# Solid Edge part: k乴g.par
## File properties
Author: priit
Template: Normal.par
Last saved by: Anon
Revision: 5
Application: Solid Edge
Accuracy: 0,990
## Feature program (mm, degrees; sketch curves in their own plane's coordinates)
sketch for "unnamed Protrusion 1" plane through (0, 0, 0) normal (0, -1, 0) x-axis (1, 0, 0)
  circle centre (0, 0) radius 2.25
extrude "unnamed Protrusion 1" add finite 7.5 symmetric
sketch for "ExtrudedCutout_1" plane through (0, 0, 0) normal (0, -1, 0) x-axis (1, 0, 0)
  circle centre (0, 0) radius 2.25
extrude "ExtrudedCutout_1" cut finite 3.5 symmetric
swept protrusion "unnamed SweptProtrusion 1"
swept protrusion "unnamed SweptProtrusion 2"
sketch for "ExtrudedProtrusion_4" plane through (0, 0, 0) normal (0, 0, 1) x-axis (1, 0, 0)
  line (-11.5, 6.8909) -> (-11.5, -7.5752)
  line (-8.5, -7.5752) -> (-8.5, 6.8909)
extrude "ExtrudedProtrusion_4" add finite 15 along -normal
fillet "Round_1" radius 1
fillet "Round_2" radius 0.5
sketch used by "ExtrudedProtrusion_5" plane through (0, -0.0341, 7.5811) normal (0.896951, 0, 0.442129) x-axis (0, 1, 0)
extrude "ExtrudedProtrusion_5" add finite 0.5 along +normal
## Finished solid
Body 1: solid body, 36 faces, 71 edges, 39 vertices.
  Faces by surface: cylinder 15, plane 14, torus 6, spline 1
  Edges by curve: circle 35, line 25, intersection 11
Bounding box of the edges (mm; curved faces can reach further): 13.750 x 17.466 x 24.148, from (-11.5, -9.0752, -15) to (2.25, 8.3909, 9.1476).
Cylindrical faces by radius (mm): R0.5 x3, R1 x7, R1.5 x3, R2.25 x2
Toroidal faces (ring radius, tube radius in mm): R0.5 r1 x2, R1 r0.5 x2, R2 r1 x2
Planar faces by outward normal: +x 3, +y 2, +z 3, -x 1, -y 2, -z 1, oblique 2
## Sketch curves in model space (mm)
circle centre (0, 0, 7.5811) radius 1.5
arc centre (-10, -7.5752, 0) radius 1.5 from (-8.5, -7.5752, 0) through (-10.0444, -9.0745, 0) to (-11.5, -7.5752, 0)
line (-8.5, -7.5752, 0) -> (-8.5, 6.8909, 0)
arc centre (-10, 6.8909, 0) radius 1.5 from (-11.5, 6.8909, 0) through (-9.9556, 8.3902, 0) to (-8.5, 6.8909, 0)
line (-11.5, 6.8909, 0) -> (-11.5, -7.5752, 0)
circle centre (-10, -0.0341, 0) radius 1
spline (-10, 0, 0) -> (-6.0028, 0, 5.4705) -> (0, 0, 7.5811)
circle centre (0, 2.6936, 0) radius 1
circle centre (0, 2.6936, 0) radius 1
line (0, -2.7618, 0) -> (-8, -2.7618, 0)
arc centre (-8, -0.7618, 0) radius 2 from (-8, -2.7618, 0) through (-9.4547, -2.1343, 0) to (-10, -0.7618, 0)
line (-10, -0.7618, 0) -> (-10, 0.6936, 0)
arc centre (-8, 0.6936, 0) radius 2 from (-8, 2.6936, 0) through (-9.4547, 2.0661, 0) to (-10, 0.6936, 0)
line (0, 2.6936, 0) -> (-8, 2.6936, 0)
circle centre (0, 0, 0) radius 2.25
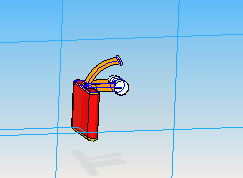
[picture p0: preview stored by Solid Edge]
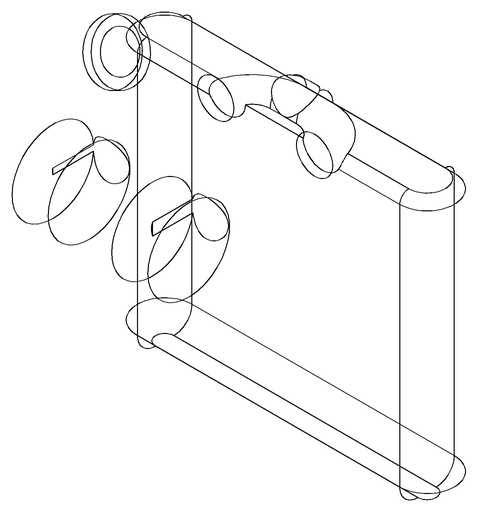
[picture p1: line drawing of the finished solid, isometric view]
